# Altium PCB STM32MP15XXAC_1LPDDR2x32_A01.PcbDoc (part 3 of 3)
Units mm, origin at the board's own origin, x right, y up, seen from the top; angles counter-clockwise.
Board outline 89 x 120 mm, 6 copper layers (Top Layer, Signal Layer 1, Signal Layer 2, Signal Layer 3, Signal Layer 4, Bottom Layer), stack 1.556 mm thick; 87 components, 99 nets, 861 pads, 454 vias.
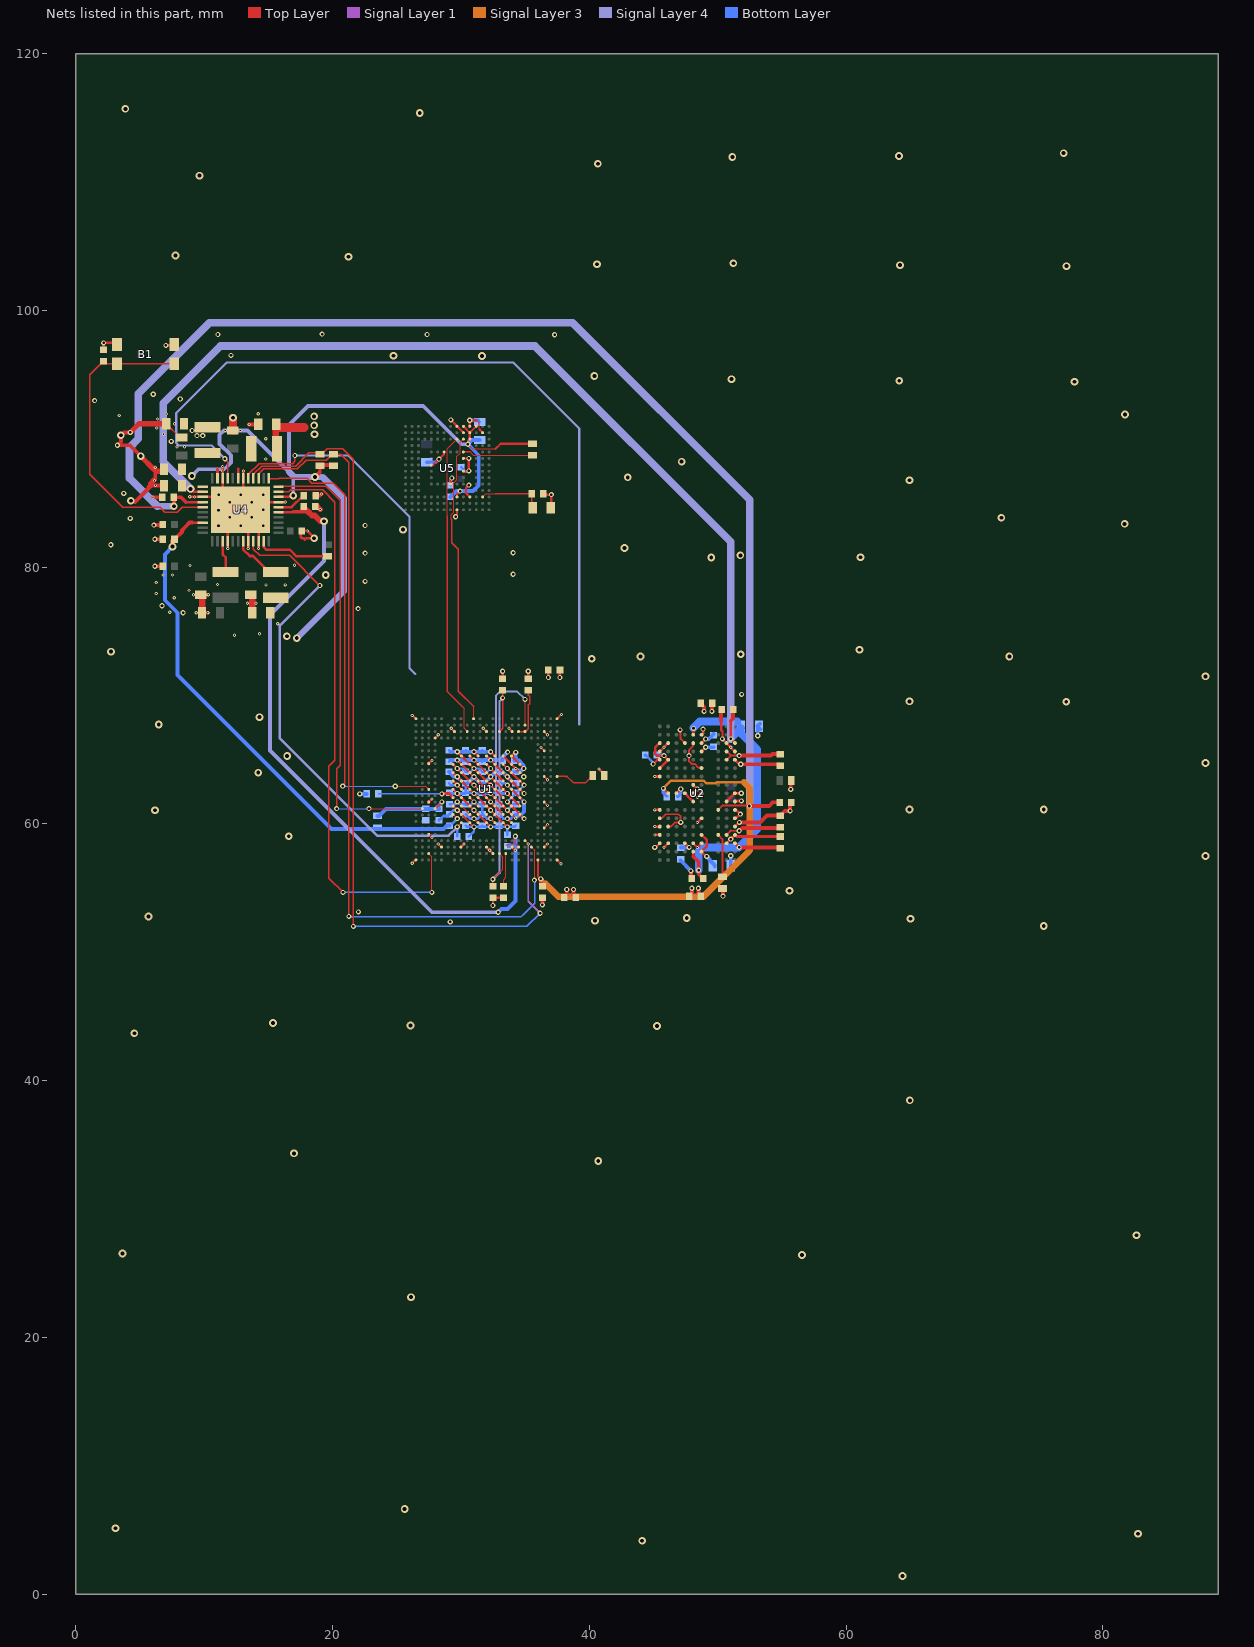
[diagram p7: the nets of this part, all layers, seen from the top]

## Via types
v1: diameter 0.4, hole 0.2, Top Layer to Bottom Layer, tented both sides, 265 vias
v2: diameter 0.6, hole 0.3, Top Layer to Bottom Layer, tented both sides, 102 vias
v3: diameter 0.25, hole 0.1, Top Layer to Signal Layer 1, tented top, 82 vias
v4: diameter 0.25, hole 0.1, Top Layer to Signal Layer 1, tented both sides, 5 vias

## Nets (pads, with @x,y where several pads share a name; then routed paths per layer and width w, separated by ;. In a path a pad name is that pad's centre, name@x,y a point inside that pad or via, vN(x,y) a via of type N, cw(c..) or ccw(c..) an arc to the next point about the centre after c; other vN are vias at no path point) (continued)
GND: B1.1 B1.2 C1.2 C2.2 C3.2 C4.2 C5.2 C6.2 C7.2 C8.2 C9.2 C10.2 C11.2 C12.2 C15.1 C16.1 C17.2 C18.1 C25.2 C26.2 C29.1 C30.1 C31.1 C32.1 C33.1 C34.1 C35.1 C36.1 C37.1 C38.1 C39.1 C40.1 C41.1 C42.1 C43.2 C44.1 C45.1 C46.1 C47.1 C48.1 C49.1 C50.1 C51.1 C52.1 C53.1 C54.1 C55.1 C56.1 C57.1 C58.1 C61.1 C66.1 C67.1 C68.1 C69.1 C70.1 C71.1 C75.1 C76.1 C77.1 C78.1 C79.1 C80.1 C81.1 C82.1 C83.1 C84.1 C92.1 C94.1 C95.1 C96.1 R26.1 R27.2 R29.1 U1.1A3 U1.1A5 U1.1A7 U1.1B2 U1.1B4 U1.1B6 U1.1B8 U1.1C1 U1.1C3 U1.1C5 U1.1C7 U1.1C9 U1.1D2 U1.1D4 U1.1D6 U1.1D8 U1.1E1 U1.1E3 U1.1E5 U1.1E7 U1.1E9 U1.1F2 U1.1F4 U1.1F6 U1.1F8 U1.1G1 U1.1G3 U1.1G5 U1.1G7 U1.1G9 U1.1H2 U1.1H4 U1.1H6 U1.1H8 U1.1J3 U1.1J5 U1.1J7 U1.A1 U1.A23 U1.AA5 U1.AA8 U1.AA12 U1.AA16 U1.AA21 U1.AB13 U1.AC1 U1.AC23 U1.C7 U1.C12 U1.C16 U1.C21 U1.D4 U1.F21 U1.H3 U1.K21 U1.P3 U1.P21 U1.V21 U1.W3 U2.C2 U2.C5 U2.C6 U2.C9 U2.D1 U2.D10 U2.E1 U2.E10 U2.F5 U2.G10 U2.H2 U2.J1 U2.J5 U2.J8 U2.L10 U2.M5 U2.N1 U2.N10 U2.P1 U2.P10 U2.R2 U2.R5 U2.R6 U2.R9 U4.6 U4.10 U4.15 U4.26 U4.30 U4.32 U4.41 U4.ep U5.A6 U5.C4 U5.E7 U5.G5 U5.H10 U5.J5 U5.K8 U5.N2 U5.N5 U5.P4 U5.P6 | length 174.7
  Top Layer w0.09: 31.225,91.45 31.45,91.225 31.45,90.725
  Top Layer w0.12: U1.AA21@36.5,58.2 U1.AA21@36.545,58.2 ; U1.C21@36.5,67.185 U1.C21@36.5,67.2 ; U2.J8@46.8,62.365 U2.J8@46.8,62.4 ; U2.M5@48.709,64.35 U2.M5@48.75,64.35 U2.M5@48.75,64.385 ; C3.2@50.275,68.835 C3.2@50.31,68.87
  Top Layer w0.127: C29.1@7.05,91.175 8.125,90.1 C18.1@8.25,90.1 ; C11.2@47.775,54.375 C11.2@48,54.6 ; C1.2@47.925,55.8 C1.2@47.975,55.75 ; v1(49.55,68.775) v1@49.575,68.8
  Top Layer w0.15: v3(36.25,65.95) U1.F21@36.5,65.7 ; U1.AA21@36.5,58.2 v3(36.75,58.45) ; U1.V21@36.5,59.7 v3(36.75,59.95) ; U1.P21@36.5,61.7 v3(36.75,61.45) ; U1.K21@36.5,63.7 v3@36.735,63.465 ; U1.C21@36.5,67.185 36.742,66.943 v3@36.75,66.935 ; U1.AC23@37.5,57.2 v3(37.795,56.905) ; U1.A23@37.5,68.2 37.837,68.537 v3@37.85,68.55 ; U2.R6@48.1,66.3 48.1,66.1 47.775,65.775 v1(47.775,65.325) 47.775,64.879 47.979,64.675 48.225,64.675 48.5,64.4 48.699,64.4 U2.M5@48.75,64.35
  Top Layer w0.175: v3(26.225,56.95) 26.475,57.2 U1.AC1@26.5,57.2 ; v3(26.225,68.45) 26.25,68.45 U1.A1@26.5,68.2 ; U1.W3@27.5,59.2 v3(27.75,58.95) ; U1.P3@27.5,61.7 v3(27.75,61.95) ; U5.H10@27.7,87.975 27.85,87.975 v1(28.3,88.425) 28.7,88.825 U5.K8@28.7,88.975 ; U1.D4@28,66.7 v3(28.25,66.95) ; v3(28.25,58.45) U1.AA5@28.5,58.2 ; v1(29.225,91.475) 29.7,91 U5.P6@29.7,90.975 U5.N5@30.2,90.475 ; v3(29.25,67.45) U1.C7@29.5,67.2 ; U1.1G1@29.4,61.4 v1(29.725,61.075) U1.1H2@30.05,60.75 U1.1J3@30.7,60.1 v1(31.025,59.775) ; U1.1E1@29.4,62.7 v1(29.725,62.375) U1.1F2@30.05,62.05 U1.1G3@30.7,61.4 v1(31.025,61.075) U1.1H4@31.35,60.75 U1.1J5@32,60.1 v1(32.325,59.775) ; U1.1C1@29.4,64 v1(29.725,63.675) U1.1D2@30.05,63.35 U1.1E3@30.7,62.7 v1(31.025,62.375) U1.1F4@31.35,62.05 U1.1G5@32,61.4 v1(32.325,61.075) U1.1H6@32.65,60.75 U1.1J7@33.3,60.1 v1(33.625,59.775) ; v1(29.6,83.925) 29.7,84.025 U5.A6@29.7,84.475 ; v1(29.725,64.975) U1.1B2@30.05,64.65 U1.1C3@30.7,64 v1(31.025,63.675) U1.1D4@31.35,63.35 U1.1E5@32,62.7 v1(32.325,62.375) U1.1F6@32.65,62.05 U1.1G7@33.3,61.4 v1(33.625,61.075) U1.1H8@33.95,60.75 33.975,60.75 v3(34.275,60.45) ; U5.G5@30.2,87.475 30.601,87.475 v1(30.625,87.5) v1(30.625,88.475) U5.J5@30.2,88.475 ; v1(30.625,86.4) 30.4,86.175 30.4,85.775 U5.C4@30.7,85.475 ; U1.1A3@30.7,65.3 v1(31.025,64.975) U1.1B4@31.35,64.65 U1.1C5@32,64 v1(32.325,63.675) U1.1D6@32.65,63.35 U1.1E7@33.3,62.7 v1(33.625,62.375) U1.1F8@33.95,62.05 U1.1G9@34.6,61.4 ; U5.P4@30.7,90.948 U5.P4@30.7,90.975 v1(30.7,91.45) 31.225,91.45 ; 31.45,90.725 U5.N2@31.7,90.475 ; v3(31.75,67.45) U1.C12@32,67.2 ; U1.1A5@32,65.3 v1(32.325,64.975) U1.1B6@32.65,64.65 U1.1C7@33.3,64 v1(33.625,63.675) U1.1D8@33.95,63.35 U1.1E9@34.6,62.7 v1(34.925,62.375) ; v1(32.5,53.65) C67.1@32.5,54.25 C69.1@33.325,54.25 ; U1.1A7@33.3,65.3 U1.1B8@33.95,64.65 v3(34.275,64.325) U1.1C9@34.6,64 ; v3(33.75,67.45) U1.C16@34,67.2 ; U1.1C9@34.6,63.975 U1.1C9@34.6,64 ; U1.1C9@34.625,64 U1.1C9@34.6,64 ; C82.1@36.425,85.725 36.5,85.65 v1(37.05,85.65) 37.05,84.675 C83.1@37,84.625 ; v3(40.755,64.283) R27.2@41.209,63.829 ; 50.285,67.305 50.376,67.213 v1(50.375,66.625) 50.376,66.612 U2.R2@50.692,66.296
  Top Layer w0.2: C44.1@2.175,96.95 v1(2.175,97.475) 3.1,97.475 B1.1@3.225,97.35 ; v1(7.025,97.275) 7.6,97.275 B1.2@7.675,97.35 ; v4(8.882,85.482) 9.243,85.482 v4(9.25,85.475) U4.15@9.9,85.475 10.875,85.475 U4.ep@10.9,85.45 ; v3@11.45,87.825 v3(11.45,87.5) U4.10@11.45,86.925 11.45,85.875 12.125,85.2 v1(12.85,84.475) ; v3(11.85,81.45) U4.26@11.85,82.025 11.85,83.475 12.125,83.75 v1(12.85,84.475) ; v2(12.255,91.64) v2@12.381,91.514 ; v3@13.05,87.5 U4.6@13.05,86.925 13.05,85.65 U4.ep@13.05,84.675 ; v3@13.45,81.425 v3(13.45,81.45) U4.30@13.45,82.025 U4.ep@13.45,83.875 ; v3(14.25,81.45) U4.32@14.25,82.025 14.25,83.075 13.587,83.738 U4.ep@13.45,83.875 ; v3(16.325,85.075) U4.41@15.8,85.075 v1(13.725,85.075) 13.45,85.075 U4.ep@13.05,84.675 ; C51.1@17.537,82.762 17.537,82.338 17.625,82.25 17.757,82.25 17.857,82.15 17.957,82.25 v2(18.575,82.25) ; C51.1@17.6,82.825 v3(18.05,82.825) v2@18.6,82.275 ; U1.H3@27.5,64.7 v3(27.75,64.95) ; U5.E7@29.2,86.475 29.2,86.825 29.312,86.937 v1@29.325,86.95 ; U1.AA8@30,58.2 v3(30.25,58.45) ; U1.AA12@32,58.2 v3(32.25,57.95) U1.AB13@32.5,57.7 ; C66.1@33.25,71.3 v1(33.25,71.9) ; U1.AA16@34,58.2 v3(34.25,57.95) ; C68.1@35.25,71.3 v1(35.25,71.9) ; v1(37.715,71.41) C12.2@37.715,71.981 ; v1(44.975,64.675) 45.3,65 U2.N10@45.5,65 ; v3@45.103,61.105 45.105,61.105 U2.G10@45.449,61.105 ; v3@45.105,59.15 v3(45.115,59.15) U2.D10@45.5,59.15 ; v3@45.11,63.7 U2.L10@45.5,63.7 ; v3@45.113,59.8 U2.E10@45.5,59.8 ; U2.P10@45.5,65.65 45.5,65.657 45.821,65.979 46.146,66.303 U2.R9@46.157,66.314 ; v3(45.825,58.175) U2.C9@46.15,58.5 ; U2.J8@46.8,62.4 v1(47.125,62.725) ; U2.C6@48.1,58.5 v3(48.425,58.175) U2.C5@48.75,58.5 ; v3@48.418,60.118 v3(48.425,60.125) U2.F5@48.75,60.45 ; v3(48.425,62.085) U2.J5@48.744,62.405 ; U2.R5@48.75,66.3 49.065,66.615 v1@49.075,66.625 ; 50.285,67.305 50.285,68.001 ; U2.C2@50.7,58.5 v1(51.025,58.825) 51.3,59.1 51.35,59.1 51.425,59.1 51.5,59.025 C2.2@54.85,59.025 ; U2.H2@50.7,61.75 U2.J1@51.35,62.4 v1@51.83,62.4 ; U2.R2@50.7,66.3 v3(51.025,65.975) ; v3@51.025,65.97 U2.P1@51.345,65.65 ; U2.E1@51.35,59.8 51.675,60.125 v1(51.7,60.125) ; U2.N1@51.35,65 51.7,64.65 v1(51.8,64.65) 52.095,64.65 ; v1(12.85,84.475) U4.ep@13.05,84.675 ; v1(12.85,84.475) U4.ep@13.45,83.875
  Top Layer w0.3: v1(4.25,90.5) 3.75,90.5 v2(3.525,90.275) 3.525,89.775 v1(3.25,89.5) 4.225,89.5 v2(5.075,88.65) ; v2(4.3,85.175) 4.525,85.175 4.625,85.075 5.675,86.125 ; v3(6.025,85.45) C84.1@6.75,85.45 ; v1(6.1,83.275) 6.75,83.275 C41.1@6.8,83.325 C41.1@6.775,83.35 ; v3(6.144,86.744) 5.925,86.525 5.925,86.5 ; v1(6.175,80.075) C32.1@6.8,80.075 ; v1(6.175,82.175) C49.1@6.8,82.175 ; v3(6.2,87.775) 6.2,87.525 6.2,86.95 ; C46.1@6.85,86.375 v3(6.214,86.375) 5.925,86.375 ; C39.1@9.75,77.85 v3(10.325,77.85) ; C40.1@9.85,76.45 v3(10.3,76.45) ; C33.1@12.255,90.701 12.25,90.696 12.227,90.673 C33.1@12.25,90.65 C33.1@12.4,90.5 ; v3@13.5,91.125 v3(13.525,91.125) 13.95,91.125 14.075,91 C34.1@14.2,90.875 ; C43.2@18.6,85.575 18.649,85.526 C43.2@18.65,85.525 ; C43.2@18.684,85.562 19.012,85.562 v3(19.15,85.7) ; v1(36.35,53.7) C17.2@36.35,54.25 ; C9.2@38.05,54.275 38.25,54.475 v1(38.25,54.9) ; C1.2@47.925,55.8 v1(47.925,56.35) ; C11.2@48,54.6 v1(48,55) ; U2.J5@48.744,62.405 48.75,62.405 U2.J5@48.766,62.405 ; v1@49.575,68.8 C10.2@49.575,69.4 ; 50.275,67.998 C3.2@50.275,68.835 ; v1(50.423,54.387) 50.423,54.975 R29.1@50.423,54.98 ; v1(51.7,60.125) 53.315,60.125 53.84,60.65 54.85,60.65 54.862,60.662 55.225,61.025 v1(55.65,61.025) 55.65,61.625 C26.2@55.725,61.7 ; 52.095,64.65 54.775,64.65 C7.2@54.875,64.55 ; v1(55.7,62.7) R26.1@55.7,63.375 ; 5.675,86.125 5.675,86.25 5.863,86.438 ; 5.675,86.125 5.925,86.375 ; 5.863,86.438 5.925,86.5 ; 5.863,86.438 5.925,86.375 ; 5.863,86.438 5.775,86.525 6.069,86.819 6.2,86.95 ; 5.925,86.375 5.925,86.5 ; 5.925,86.5 6.157,86.732 6.2,86.775 6.2,86.95
  Top Layer w0.4: v1(4.25,90.5) 4.925,91.175 6.325,91.175 C29.1@7.05,91.175 ; v2(5.075,88.65) 6.075,87.65 6.2,87.525 6.25,87.475 C42.1@6.6,87.475 ; C52.1@18.751,84.801 v3(19.053,84.5)
  Top Layer w0.5: C39.1@9.75,77.85 9.85,77.75 C40.1@9.85,76.45 ; C31.1@13.625,77.85 13.625,77.75 13.75,77.625 13.75,77.2 C38.1@13.75,76.45
  Top Layer w0.6: C33.1@12.25,90.65 12.25,90.696 12.25,91.635 v2(12.255,91.64)
  Bottom Layer w0.127: C16.1@53.125,67.525 53.166,67.566 C16.1@53.225,67.625
  Bottom Layer w0.175: C35.1@29.075,64.85 C35.1@29.2,64.975 ; C37.1@30.225,63.175 C37.1@30.375,63.175 C37.1@30.525,63.175 ; C96.1@30.375,59.875 C96.1@30.475,59.775 ; C47.1@30.625,59.025 31.025,59.425 v1(31.025,59.775) ; C81.1@31.325,91.45 C81.1@31.475,91.3 ; C36.1@31.525,63.175 C36.1@31.675,63.175 C36.1@31.825,63.175 ; C76.1@31.55,64.975 C76.1@31.675,64.85 C76.1@31.8,64.975 ; C95.1@31.575,59.775 C95.1@31.675,59.875 C95.1@31.775,59.775 ; C45.1@32.725,64.075 C45.1@32.975,64.075 C45.1@33.225,64.075 ; C55.1@32.875,59.775 C55.1@32.975,59.875 C55.1@33.075,59.775 ; C53.1@33.25,65.2 33.25,64.975 C53.1@33.275,64.95 ; C57.1@34.125,63.175 C57.1@34.275,63.175 ; C54.1@34.175,59.775 C54.1@34.275,59.875
  Bottom Layer w0.2: C58.1@28.3,60.35 C58.1@28.3,60.275 28.65,60.625 28.975,60.625 C70.1@29.125,60.775 29.425,61.075 v1(29.725,61.075) ; C94.1@29.125,62.425 29.175,62.375 v1(29.725,62.375) 30.325,62.375 C48.1@30.375,62.425 ; C80.1@29.2,86.375 29.2,86.825 29.312,86.937 v1@29.325,86.95 ; C78.1@30.025,87.8 30.35,87.475 30.6,87.475 v1(30.625,87.5) ; C37.1@30.375,63.175 C48.1@30.375,62.425 ; C96.1@30.475,59.775 v1(31.025,59.775) C95.1@31.575,59.775 ; C92.1@31.675,62.425 C92.1@31.725,62.375 ; C95.1@31.775,59.775 v1(32.325,59.775) C55.1@32.875,59.775 ; C55.1@33.075,59.775 v1(33.625,59.775) ; C71.1@33.625,59.175 v1(33.625,59.775) ; v1(33.625,61.075) 34.075,61.525 C56.1@34.275,61.525 ; v1(33.625,62.375) 33.025,62.375 C77.1@32.975,62.425 32.375,62.425 v1(32.325,62.375) C92.1@31.725,62.375 ; C54.1@34.175,59.775 v1(33.625,59.775) ; C6.2@44.402,65.36 44.982,64.78 44.982,64.675 v1@44.982,64.652 ; C48.1@30.375,62.425 30.975,62.425 v1(31.025,62.375) 31.675,62.375 C92.1@31.725,62.375
  Bottom Layer w0.3: v1(22.125,62.35) C61.1@22.675,62.35 ; C79.1@27.35,88.175 28.05,88.175 v1(28.3,88.425) ; C75.1@29.075,64.075 29.475,63.675 v1(29.725,63.675) C37.1@30.225,63.175 ; C35.1@29.2,64.975 v1(29.725,64.975) 30.375,64.975 v1(31.025,64.975) C76.1@31.55,64.975 ; C37.1@30.525,63.175 v1(31.025,63.675) C36.1@31.525,63.175 ; v1(30.7,91.45) C81.1@31.325,91.45 ; C76.1@31.8,64.975 v1(32.325,64.975) C53.1@33.25,64.975 ; C36.1@31.825,63.175 v1(32.325,63.675) C45.1@32.725,64.075 ; C45.1@33.225,64.075 v1(33.625,63.675) C57.1@34.125,63.175 ; C53.1@33.25,65.2 v1(33.65,65.6) ; C6.2@44.364,65.36 C6.2@44.402,65.36 ; C25.2@46.905,62.174 47.127,62.396 47.127,62.725 v1@47.127,62.727 ; C4.2@47.102,57.177 v1@47.927,56.352 ; v1@49.064,66.627 49.309,66.627 49.629,66.946 C5.2@49.685,67.003 ; C15.1@51.027,56.717 51.027,56.75 51.027,57.525 v1@51.027,57.527 ; C16.1@53.103,67.628 53.166,67.566 C16.1@53.348,67.383 ; v1(53.125,66.875) C16.1@53.125,67.525 ; C16.1@53.152,67.667 53.167,67.683 C16.1@53.295,67.81
  other v1: 29.175,52.375 22.025,53.15 51.025,57.525 51.845,62.4 34.9,63.675 49.06,66.62 51.875,70.1 8.375,76.45 22,76.775 6.725,77 22.55,78.9 34.075,79.45 22.55,81.1 34.075,81.125 2.75,81.75 11.125,83.225 12.875,83.225 14.6,83.225 22.55,83.25 4.25,83.801 12,83.875 13.725,83.875 11.125,84.45 14.6,84.475 12,85.075 11.15,85.65 12.875,85.65 14.6,85.65 3.75,85.75 29.3,86.95 7.45,89.8 1.475,92.975 8.15,93.1 6.05,93.475 12.1,96.5 37.3,98.1 11.075,98.125 27.375,98.125 19.2,98.15
  other v2: 64.4,1.425 44.125,4.175 82.75,4.725 3.1,5.15 25.625,6.65 26.125,23.15 56.575,26.425 3.65,26.55 82.625,27.975 40.7,33.75 17,34.35 64.975,38.475 4.575,43.7 45.275,44.275 26.075,44.3 15.375,44.5 75.4,52.05 40.452,52.475 65.025,52.625 47.597,52.681 5.675,52.8 55.6,54.8 88,57.5 16.6,59.05 6.175,61.075 64.95,61.125 75.4,61.125 14.225,64 88,64.75 16.475,65.3 6.475,67.75 14.325,68.325 77.15,69.525 64.95,69.55 88,71.5 40.2,72.875 44,73.05 72.725,73.05 51.8,73.225 2.75,73.425 61.05,73.575 19.475,79.4 49.5,80.75 61.125,80.775 51.775,80.925 42.75,81.5 25.5,82.925 81.7,83.375 72.1,83.85 64.95,86.775 43,87 47.2,88.225 81.725,91.9 77.8,94.45 64.15,94.525 51.075,94.65 40.4,94.9 31.65,96.45 24.75,96.475 77.175,103.45 64.2,103.525 40.6,103.6 51.225,103.675 21.25,104.175 7.775,104.275 9.65,110.5 40.675,111.425 51.15,111.95 64.125,112.025 76.95,112.25 26.8,115.375 3.875,115.7
  other v3: 45.105,59.8 45.105,61.1 36.75,63.45 45.105,63.7 45.825,65.975 36.75,66.95 37.85,68.525 12.375,74.7 14.325,74.825 15.75,75.6 9.4,76.45 13.375,77.2 14.05,77.2 7.675,77.625 9.175,77.85 8.825,78.175 14.825,78.625 16.325,78.625 11.05,78.65 6.8,79.4 7.55,79.4 8.911,80.125 17.05,80.15 13.075,87.5 11.45,87.85 14.8,88.425 7.9,89.375 8.475,89.375 14.8,90 6.85,90.35 11.65,90.65 12.825,90.65 6.325,90.85 7.7,91.175 6.375,91.55 3.4,91.825 7.05,91.925 14.225,91.95
  other v4: 7.325,76.5 6.275,77.95 6.275,78.8
I2C4_SCL: R37.2 U1.Y18 U4.4 | length 66.8
  Top Layer w0.09: U1.Y18@35,58.7 v3(35.25,58.45)
  Top Layer w0.1: U4.4@13.85,86.925 13.85,87.237 14.488,87.875 17.125,87.875 18.15,88.9 19.025,88.9 19.26,88.9 19.6,89.24 20.81,89.24 21.638,88.413 v1(21.638,52.025)
  Signal Layer 1 w0.1: v3(35.25,58.45) 35.25,53.975 v1(36.175,53.05)
  Bottom Layer w0.1: v1(21.638,52.025) 35.15,52.025 v1(36.175,53.05)
I2C4_SDA: R38.2 U1.AA19 U4.3 | length 63.2
  Top Layer w0.09: U1.AA19@35.5,58.2 35.75,57.95 v1@35.75,55.625
  Top Layer w0.1: U4.3@14.25,86.925 14.25,87.267 14.658,87.675 17.275,87.675 17.95,88.35 19.525,88.35 20.012,88.838 R38.2@19.975,88.875 ; R38.2@20.074,88.813 20.637,88.813 21.288,88.162 v1(21.288,52.8)
  Bottom Layer w0.1: 34.813,52.888 35.75,53.825 35.75,55.625 v1@35.75,55.775
  Bottom Layer w0.12: v1(21.288,52.8) 21.323,52.765 34.69,52.765 34.813,52.888
  other v1: 35.725,55.625
NetB1_3: B1.3 B1.4 C44.2 U4.17 | length 24.9
  Top Layer w0.1: B1.4@7.675,95.85 B1.3@3.225,95.85 2.175,95.85 1.95,95.85 1.1,95 1.1,87.25 3.675,84.675 6.575,84.675 6.95,84.3 7.925,84.3 8.3,84.675 U4.17@9.9,84.675
NetC43_1: C43.1 U4.40 | length 2.2
  Top Layer w0.2: U4.40@15.8,84.675 16.828,84.675 C43.1@17.689,85.536
NetC61_2: C61.2 U1.1F1 | length 6
  Top Layer w0.2: v1@28.55,62.375 29.075,62.375 U1.1F1@29.4,62.05
  Top Layer w0.3: v1@28.475,62.35 v1(28.525,62.35) v1@28.55,62.375
  Bottom Layer w0.1: C61.2@23.575,62.35 v1(28.525,62.35)
NetC68_2: C68.2 U1.C17 U1.C18 | length 3.9
  Top Layer w0.1: U1.C17@34.5,67.2 U1.C18@35,67.2 35.025,67.2 35.25,67.425 35.25,69.275 35.35,69.375 35.35,69.945 35.25,70.045 C68.2@35.25,70.4
NetC69_2: C69.2 U1.AB15 | length 2.6
  Top Layer w0.09: C69.2@33.325,55.15 33.325,55.675 33.5,55.85 U1.AB15@33.5,57.7
NetC82_2: C82.2 C83.2 U5.C2 | length 5.1
  Top Layer w0.09: U5.C2@31.7,85.475 31.95,85.725 32.7,85.725
  Top Layer w0.1: 32.7,85.725 C82.2@35.525,85.725 35.525,84.7 C83.2@35.6,84.625
NetL1_1: L1.1 U4.7 | length 0.7
  Top Layer w0.2: U4.7@12.65,86.925 12.65,87.672
NetL2_1: L2.1 U4.11 | length 0.7
  Top Layer w0.2: U4.11@11.05,86.925 11.05,87.65
NetL3_1: L3.1 U4.29 | length 3.9
  Top Layer w0.2: U4.29@13.05,82.025 13.05,81.39 13.565,80.875 13.8,80.875 15.05,79.625 L3.1@15.575,79.625
NetL4_1: L4.1 U4.25 | length 2.4
  Top Layer w0.2: U4.25@11.45,82.025 11.45,81 11.675,80.775 L4.1@11.675,79.725
NetR27_1: R27.1 U1.K23 | length 3.3
  Top Layer w0.1: U1.K23@37.5,63.7 38.165,63.7
  Top Layer w0.12: 38.165,63.7 38.275,63.7 38.752,63.223 39.723,63.223 R27.1@40.275,63.775 R27.1@40.362,63.862
NetR29_2: R29.2 U2.D3 | length 3.4
  Top Layer w0.15: U2.D3@50.05,59.15 50.375,58.824 R29.2@50.375,55.875
NetR40_1: R40.1 U5.K5 | length 5.5
  Top Layer w0.09: 30.725,88.975 30.975,88.725 R40.1@35.575,88.725
  Top Layer w0.1: U5.K5@30.2,88.975 30.725,88.975
NetR43_1: R43.1 U4.33 | length 5.7
  Top Layer w0.2: U4.33@14.65,82.025 14.65,81.561 14.836,81.375 16.675,81.375 17.2,80.85 R43.1@19.625,80.85
NRST: U1.M3 U4.1 | length 36
  Top Layer w0.09: v1(24.89,62.94) 27.26,62.94 U1.M3@27.5,62.7
  Top Layer w0.1: U4.1@15.05,86.875 15.82,86.875 15.87,86.925 18.025,86.925 18.4,86.55 20.075,86.55 20.975,85.65 20.975,63.125 v1(20.8,62.95)
  Bottom Layer w0.09: v1(20.8,62.95) 24.88,62.95 v1(24.89,62.94)
PA0_WKUP: U1.AB3 U4.43 | length 46
  Top Layer w0.09: U1.AB3@27.5,57.7 27.75,57.45 v1(27.75,54.675)
  Top Layer w0.1: U4.43@15.8,85.875 16.614,85.875 16.764,86.025 19.25,86.025 20.2,85.075 20.2,64.975 19.725,64.5 19.725,55.775 v1(20.825,54.675)
  Bottom Layer w0.1: v1@20.8,54.675 v1(20.825,54.675) v1(27.75,54.675)
PWR_ON: U1.R2 U4.44 | length 36.1
  Top Layer w0.09: v1@22.825,61.2 v1(22.85,61.2) U1.R2@27,61.2
  Top Layer w0.1: U4.44@15.85,86.225 15.925,86.3 19.525,86.3 20.6,85.225 20.6,64.575 20.325,64.3 v1(20.325,61.2)
  Bottom Layer w0.09: v1(20.325,61.2) v1(22.85,61.2)
SDMMC2_CK: U1.C9 U5.M6 | length 23.7
  Top Layer w0.09: 28.95,84 28.95,89.225 U5.M6@29.7,89.975 ; 30.137,69.138 30.25,69.025 30.25,67.45 U1.C9@30.5,67.2
  Top Layer w0.13: 28.95,84 28.95,70.325 30.137,69.138
SDMMC2_CMD: U1.A10 U5.M5 | length 22.9
  Top Layer w0.09: 29.255,83.745 29.255,84.068 29.46,84.273 29.46,86.574 29.7,86.814 29.7,88.636 29.95,88.886 29.95,89.725 U5.M5@30.2,89.975 ; U1.A10@31,68.2 31,69.15
  Top Layer w0.13: 29.255,83.745 29.3,83.7 29.3,81.9 29.8,81.4 29.8,70.35 31,69.15
VDD: C38.2 C42.2 C47.2 C48.2 C80.2 C81.2 C92.2 C94.2 C95.2 C96.2 L3.2 R37.1 R38.1 R40.2 U1.1F3 U1.1G2 U1.1G4 U1.1H3 U1.1H5 U1.1J2 U1.1J4 U1.1J6 U1.B18 U4.13 U4.31 U4.42 U5.C6 U5.M4 U5.N4 U5.P3 U5.P5 | length 133
  Top Layer w0.09: v1(30.55,89.575) 30.9,89.225 32.7,89.225 ; U1.B18@35,67.7 v1(35,69.7) v1@35,69.8
  Top Layer w0.1: U4.31@13.85,82.025 13.85,81.4 14.325,80.925 16.675,80.925 v1(19.025,78.575)
  Top Layer w0.12: v1(29.725,59.775) U1.1J2@30.05,60.1 ; v1(29.725,61.725) U1.1G2@30.05,61.4 U1.1H3@30.7,60.75 v1(31.025,60.425) U1.1J4@31.35,60.1 ; U1.1F3@30.7,62.05 v1(31.025,61.725) U1.1G4@31.35,61.4 ; U1.1H5@32,60.75 v1(32.325,60.425) U1.1J6@32.65,60.1
  Top Layer w0.175: U5.C6@29.7,85.475 29.7,85.675 v1(29.95,85.925) ; U5.P5@30.2,90.975 U5.N4@30.7,90.475 ; v1(30.55,89.575) 30.55,89.825 U5.M4@30.7,89.975 U5.N4@30.7,90.475 ; U5.P3@31.2,90.975 U5.N4@30.7,90.475 ; 32.7,89.225 33.1,89.625 R40.2@35.575,89.625
  Top Layer w0.2: U4.42@15.8,85.475 v2@16.85,85.475 ; v2@16.85,85.475 v2(16.95,85.575) ; v2@16.85,85.475 v2(16.95,85.575) ; v2(16.95,85.575) v2(16.95,85.575) 16.95,85.579 v2(16.95,85.575)
  Top Layer w0.25: 19,87.375 19.025,87.4 R37.1@19.025,87.9
  Top Layer w0.3: v2@18.65,87.15 v2(18.65,87.025) 19,87.375 ; R37.1@19.325,87.95 20.074,87.95 R38.1@20.175,87.95
  Signal Layer 4 w0.15: 32.6,60.675 32.725,60.8 32.725,69.975 33.075,70.325 34.375,70.325 v1(35,69.7)
  Signal Layer 4 w0.2: 16.95,87.1 17.025,87.025 ; v1(19.025,78.575) 15.9,75.45 15.9,66.675 23.475,59.1 29.05,59.1 v1(29.725,59.775)
  Signal Layer 4 w0.3: v2(9.05,87.1) 9.575,87.625 11.575,87.625 12.1,88.15 12.1,88.725 11.217,89.608 11.217,90.317 11.55,90.65 13.4,90.65 16.625,87.425 16.625,91.075 18.1,92.55 27.075,92.55 30.05,89.575 v1(30.55,89.575) ; v2(16.95,85.575) 16.95,87.1
  Signal Layer 4 w0.5: 16.625,87.425 16.95,87.1 ; 17.025,87.025 v2(18.65,87.025) 19.225,87.025 20.875,85.375 20.875,78.125 v2(17.225,74.475)
  Bottom Layer w0.175: C47.2@29.725,59.025 v1(29.725,59.775)
  Bottom Layer w0.2: C94.2@29.125,61.525 29.525,61.525 v1(29.725,61.725) 29.925,61.525 C48.2@30.375,61.525 ; C96.2@30.375,60.775 30.725,60.425 v1(31.025,60.425) 31.325,60.425 C95.2@31.675,60.775 ; C48.2@30.4,61.5 30.8,61.5 v1(31.025,61.725) 31.225,61.525 C92.2@31.675,61.525 C95.2@31.675,60.775 ; v1(32.325,60.425) 32.025,60.425 C95.2@31.675,60.775
  Bottom Layer w0.3: C80.2@29.2,85.475 29.65,85.925 v1(29.95,85.925) 30.95,85.925 31.4,86.375 31.4,88.725 v1(30.55,89.575) 30.875,89.9 C81.2@31.475,89.9
  other v2: 16.45,74.625
VDD1_DDR: C1.1 C2.1 C3.1 C16.2 C46.2 U2.B6 U2.C1 U2.R1 U2.T6 U4.14 | length 105.7
  Top Layer w0.12: v1@48.1,67.434 48.12,67.454 v1@48.124,67.459
  Top Layer w0.15: v1@48.1,67.425 v1(48.125,67.45)
  Top Layer w0.175: v1(51.025,66.625) 51.025,68.025
  Top Layer w0.2: 9.175,85.875 U4.14@9.9,85.875 ; U2.B6@48.1,57.85 48.103,57.846 48.103,57.479 ; U2.T6@48.1,66.95 v1@48.1,67.434 ; v1(51.025,66.625) U2.R1@51.35,66.3 ; U2.C1@51.35,58.5 v1(51.675,58.175)
  Top Layer w0.3: 48.103,57.479 48.535,57.048 48.535,56.4 v1@48.535,56.395 ; v1@48.53,56.39 48.53,56.087 48.871,55.746 C1.1@48.873,55.744 ; 51.025,68.025 51.2,68.2 51.2,68.86 C3.1@51.21,68.87 ; v1(51.675,58.175) C2.1@54.875,58.175
  Signal Layer 4 w0.6: v2(8.95,86.1) 6.825,88.225 6.825,92.775 11.275,97.225 35.775,97.225 51.025,81.975 v1(51.025,66.625)
  Bottom Layer w0.3: v1@51.027,66.627 v1@51.027,66.656 ; C16.2@51.537,67.975 C16.2@51.706,67.806 ; C16.2@51.737,67.661 C16.2@51.8,67.599 ; 51.817,67.058 C16.2@51.817,67.447
  Bottom Layer w0.6: v1@48.1,67.474 48.611,67.985 51.527,67.985 C16.2@51.537,67.975 ; v1@48.525,56.4 48.525,57.9 48.802,58.177 51.652,58.177 51.662,58.187 53.075,59.6 53.075,65.8 51.817,67.058 ; v1@51.027,66.656 C16.2@51.817,67.447
  other v1: 48.525,56.4
VDD2_DDR: C4.1 C5.1 C6.1 C7.1 C8.1 C9.1 C10.1 C11.1 C12.1 C15.2 C29.2 C45.2 C53.2 C54.2 C55.2 C56.2 C57.2 L2.2 U1.1A8 U1.1B7 U1.1B9 U1.1C8 U1.1D9 U1.1E8 U1.1F9 U1.1G8 U1.1H9 U1.1J8 U2.B5 U2.C7 U2.C10 U2.D2 U2.D5 U2.E9 U2.F1 U2.F10 U2.G1 U2.H1 U2.H6 U2.J6 U2.J7 U2.K6 U2.M10 U2.N2 U2.N9 U2.P2 U2.P5 U2.R7 U2.R10 U2.T5 U4.9 | length 116.3
  Top Layer w0.1: v1(11.625,88.45) 11.85,88.225 U4.9@11.85,86.925
  Top Layer w0.12: U2.B5@48.75,57.85 U2.B5@48.75,57.855
  Top Layer w0.15: U1.1H9@34.6,60.75 v1(34.925,60.425) ; U1.1F9@34.6,62.05 v1(34.925,61.725) ; U1.1D9@34.6,63.35 v1(34.925,63.025) ; U2.F10@45.5,60.45 45.638,60.45 45.948,60.76 46.95,60.76 47.125,60.585 v1(47.125,60.13) v1@47.125,60.125 ; U2.E9@46.15,59.8 46.361,59.8 46.671,60.11 v1@47.11,60.11 ; v1@47.076,67.31 47.125,67.261 47.125,66.625 U2.R7@47.45,66.3 ; U2.N2@50.7,65 51.025,65.325 v1(51.675,65.325) ; U2.P2@50.735,65.615 51.01,65.34 ; 51.025,59.475 v1(51.675,59.475) v1@51.7,59.475
  Top Layer w0.175: U1.1B7@33.3,64.65 v1(33.625,64.325) U1.1C8@33.95,64 U1.1D9@34.6,63.35 ; v1(33.625,60.425) U1.1J8@33.95,60.1 ; v1(33.625,61.725) U1.1G8@33.95,61.4 U1.1H9@34.6,60.75 ; v1(33.625,63.025) U1.1E8@33.95,62.7 U1.1F9@34.6,62.05 ; v1(34.275,65.575) 34.225,65.575 U1.1A8@33.95,65.3 U1.1B9@34.6,64.65 ; U1.1B9@34.6,64.625 U1.1B9@34.6,64.65 ; v1@34.9,64.35 U1.1B9@34.6,64.65 ; 45.263,65.325 v1(45.825,65.325)
  Top Layer w0.2: v1(36.815,71.41) C12.1@36.815,71.981 ; v1@45.08,58.175 v1(45.1,58.175) 45.175,58.175 U2.C10@45.499,58.499 ; 45.263,65.325 45.14,65.448 45.14,65.963 U2.R10@45.481,66.304 ; U2.M10@45.5,64.35 U2.N9@46.15,65 v1(45.825,65.325) ; U2.C7@47.45,58.5 v1@47.772,58.177 ; U2.J7@47.45,62.4 47.778,62.075 ; U2.K6@48.1,63.05 v1(48.425,62.725) U2.J6@48.1,62.4 47.778,62.075 ; U2.H6@48.105,61.744 U2.H6@48.1,61.75 47.778,62.075 ; U2.B5@48.75,57.837 v1@49.131,57.456 ; U2.B5@48.75,57.855 49.17,58.275 49.17,58.745 U2.D5@48.765,59.15 ; U2.P5@48.75,65.65 49.068,65.968 v1@49.074,65.974 ; U2.T5@48.75,66.95 48.875,67.075 v1@48.875,67.372 ; U2.D2@50.7,59.15 51.025,59.475 ; U2.F1@51.35,60.45 51.449,60.45 v1(51.775,60.775) 51.45,61.1 U2.G1@51.35,61.1 ; U2.H1@51.35,61.75 51.39,61.79 v1@51.85,61.79
  Top Layer w0.3: v1(38.775,54.9) 38.775,54.45 C9.1@38.95,54.275 ; v1@47.772,58.177 47.775,58.177 v1@47.797,58.177 ; v1(48.5,55) 48.5,54.55 C11.1@48.675,54.375 ; C10.1@48.675,69.4 48.95,69.125 v1(48.95,68.775) ; U2.B5@48.75,57.837 U2.B5@48.75,57.85 ; v1(51.675,65.325) 54.154,65.325 54.279,65.45 C7.1@54.875,65.45 ; v1@51.7,59.475 51.925,59.7 C8.1@54.825,59.7
  Signal Layer 4 w0.175: v1@11.7,88.45 v1(11.625,88.45) 10.6,89.475 8.037,89.475 7.838,89.675 7.838,92.012 11.775,95.95 34.075,95.95 39.225,90.8 39.225,67.775
  Bottom Layer w0.127: 34.7,60.65 34.7,60.725
  Bottom Layer w0.175: C45.2@32.975,63.175 33.475,63.175 v1(33.625,63.025) 33.898,62.752 33.973,62.752 34.275,62.45 C56.2@34.275,62.425 ; v1(33.625,61.725) C56.2@34.275,62.375 ; v1(33.625,64.325) 33.875,64.075 C57.2@34.275,64.075 ; C54.2@34.275,60.775 C54.2@34.325,60.725 ; C53.2@34.275,65.05 C53.2@34.296,65.004 ; v1@34.9,63 34.325,62.425 C56.2@34.275,62.425 ; v1(34.925,61.725) C56.2@34.275,62.375 ; C56.2@34.275,62.375 C56.2@34.275,62.425
  Bottom Layer w0.2: C55.2@32.975,60.775 33.325,60.425 v1(33.625,60.425) 33.925,60.425 C54.2@34.275,60.775 ; 34.7,60.65 v1(34.925,60.425)
  Bottom Layer w0.25: v1@49.064,65.977 49.675,65.977 C5.1@49.694,65.977
  Bottom Layer w0.3: C53.2@34.175,64.95 34.525,64.95 34.9,64.575 v1(34.9,64.325) ; C57.2@34.275,64.075 34.65,64.075 v1@34.887,64.312 ; C53.2@34.275,65.05 v1(34.275,65.575) ; C54.2@34.325,60.725 34.7,60.725 34.925,60.95 v1(34.925,61.725) ; C6.1@45.264,65.36 45.818,65.36 v1@45.838,65.339 ; C4.1@47.152,58.177 47.775,58.177 v1@47.777,58.177 ; v1@49.13,57.455 49.73,56.855 49.782,56.803 49.782,56.75 C15.2@49.782,56.683
  other v1: 49.15,57.475 47.775,58.175 51.85,61.8 49.062,65.975 47.075,67.325 48.86,67.385 9.45,90.25 9.9,90.25 9.075,90.65
VDD_CORE: C30.2 C34.2 C35.2 C36.2 C37.2 C75.2 C76.2 C77.2 L1.2 U1.1A2 U1.1A4 U1.1A6 U1.1B1 U1.1B3 U1.1B5 U1.1C2 U1.1C4 U1.1C6 U1.1D1 U1.1D3 U1.1D5 U1.1D7 U1.1E2 U1.1E4 U1.1E6 U1.1F5 U1.1F7 U1.1G6 U1.1H7 U4.5 | length 54.1
  Top Layer w0.1: U4.5@13.45,86.925 13.45,87.237 14.288,88.075 16.9,88.075 17.075,88.25 v1(17.075,88.7)
  Top Layer w0.175: U1.1D1@29.4,63.35 v1(29.725,63.025) U1.1E2@30.05,62.7 ; U1.1B1@29.4,64.65 v1(29.725,64.325) U1.1C2@30.05,64 U1.1D3@30.7,63.35 v1(31.025,63.025) U1.1E4@31.35,62.7 U1.1F5@32,62.05 v1(32.325,61.725) U1.1G6@32.65,61.4 U1.1H7@33.3,60.75 ; v1(29.725,65.625) U1.1A2@30.05,65.3 U1.1B3@30.7,64.65 v1(31.025,64.325) U1.1C4@31.35,64 U1.1D5@32,63.35 v1(32.325,63.025) U1.1E6@32.65,62.7 U1.1F7@33.3,62.05 ; v1(31.025,65.625) U1.1A4@31.35,65.3 ; U1.1B5@32,64.65 v1(32.325,64.325) U1.1C6@32.65,64 U1.1D7@33.3,63.35 ; v1(32.325,65.625) U1.1A6@32.65,65.3
  Top Layer w0.5: C34.2@15.6,90.875 15.6,89.3 L1.2@15.675,89.225
  Top Layer w0.7: C34.2@15.675,90.875 17.775,90.875
  Signal Layer 4 w0.175: v1(17.075,88.7) 21.225,88.7 26,83.925 26,72.125 26.45,71.675
  Bottom Layer w0.175: C75.2@29.075,63.175 29.225,63.025 v1(29.725,63.025) ; C35.2@29.075,65.75 C35.2@29.2,65.625 ; v1(29.725,64.325) 30.125,64.325 C37.2@30.375,64.075 30.775,64.075 v1(31.025,64.325) 31.425,64.325 C36.2@31.675,64.075 32.075,64.075 v1(32.325,64.325) ; C30.2@30.25,65.625 C30.2@30.375,65.75 C30.2@30.5,65.625 ; C76.2@31.55,65.625 C76.2@31.675,65.75 C76.2@31.8,65.625
  Bottom Layer w0.2: v1(32.325,61.725) 32.525,61.525 C77.2@32.975,61.525
  Bottom Layer w0.3: C35.2@29.2,65.625 v1(29.725,65.625) C30.2@30.25,65.625 ; C30.2@30.5,65.625 v1(31.025,65.625) C76.2@31.55,65.625 ; C76.2@31.8,65.625 v1(32.325,65.625)
  other v2: 18.6,90.35 18.575,91.05 18.575,91.75
VDD_USB: C52.2 C71.2 U1.AA15 U1.AA17 U4.39 | length 57.9
  Top Layer w0.09: U1.AA15@33.5,58.2 33.75,58.45 34.25,58.45 ; v1@34.25,59.125 v1(34.25,59.05) 34.25,58.45 ; U1.AA17@34.5,58.2 34.25,58.45
  Top Layer w0.2: U4.39@15.8,84.275 16.85,84.275 ; C52.2@17.625,84.575 C52.2@17.775,84.725 C52.2@17.775,84.66 ; 16.85,84.275 18.075,84.275 18.117,84.317 18.175,84.375 18.059,84.375 17.775,84.375 16.95,84.375 16.85,84.275
  Top Layer w0.45: C52.2@17.775,84.66 17.775,84.659 18.059,84.375 18.117,84.317 18.409,84.025 18.625,84.025 19.075,83.575 v2(19.35,83.575)
  Signal Layer 4 w0.3: v2(19.35,83.575) 19.35,80.475 15.15,76.275 15.15,65.725 27.75,53.125 v1(32.9,53.125)
  Bottom Layer w0.3: v1(32.9,53.125) 33.155,53.38 33.63,53.38 34.25,54 v1(34.25,59.05) ; C71.2@33.625,58.275 34.225,58.275
VDDA: C49.2 C70.2 R41.1 U1.1H1 U4.20 | length 41.4
  Top Layer w0.09: U1.1H1@29.4,60.75 v1(29.725,60.425)
  Top Layer w0.2: 9.075,83.475 U4.20@9.9,83.475
  Top Layer w0.3: C49.2@7.7,82.175 8.275,82.75 8.275,82.873 8.55,83.148 8.55,83.155 8.87,83.475 9.075,83.475
  Top Layer w0.4: v2(7.55,81.6) 7.55,82.025 C49.2@7.7,82.175
  Bottom Layer w0.2: C70.2@29.35,60.05 v1(29.725,60.425)
  Bottom Layer w0.3: v2(7.55,81.6) 6.95,81 6.95,77.425 7.925,76.45 7.925,71.6 19.925,59.6 23.5,59.6 28.65,59.6 28.925,59.875 C70.2@29.125,59.875
VDDA_1V8: C66.2 C67.2 U1.AB14 U1.C14 | length 20.7
  Top Layer w0.09: C67.2@32.5,55.15 v1(32.5,55.7) 33.275,56.475 33.275,57.425 U1.AB14@33,57.7
  Top Layer w0.1: U1.C14@33,67.2 33.25,67.45 v1(33.25,69.825) C66.2@33.25,70.4
  Signal Layer 4 w0.1: v1@33.25,69.8 v1(33.25,69.825)
  Signal Layer 4 w0.15: 33.025,56.225 33.025,69.575 v1@33.25,69.8
  Signal Layer 4 w0.2: v1(32.5,55.7) 33.025,56.225
VREF+: C50.2 C58.2 R41.2 U1.R4 | length 6.5
  Top Layer w0.1: U1.R4@28,61.2 28.025,61.2 28.537,61.713 v1@28.575,61.75
  Bottom Layer w0.2: C58.2@28.3,61.175 28.3,61.5 v1(28.525,61.725)
  Bottom Layer w0.3: R41.2@23.5,60.625 23.625,60.625 24.175,61.175 C50.2@27.275,61.175 C58.2@28.3,61.175
VREF_DDR: C17.1 C25.1 C26.1 C84.2 U1.AC20 U2.G3 U2.J9 U4.16 | length 132.9
  Top Layer w0.12: U2.J9@46.15,62.4 U2.J9@46.15,62.422
  Top Layer w0.127: C17.1@36.225,55.275 C17.1@36.35,55.15 ; v1@36.225,55.7 v1(36.225,55.725)
  Top Layer w0.15: U1.AC20@36,57.2 36,55.925 36.213,55.712 v1@36.225,55.7 ; U2.G3@50.05,61.1 50.375,61.425 52.475,61.425 v1@52.5,61.425
  Top Layer w0.2: 8.575,85.075 U4.16@9.9,85.075 ; v1@45.782,62.789 45.785,62.786 U2.J9@46.15,62.422
  Top Layer w0.3: v2(7.65,84.75) C84.2@7.65,85.45 8.2,85.45 8.575,85.075 ; C17.1@36.225,55.275 v1@36.225,55.7 ; v1@52.5,61.4 54.025,61.4 54.325,61.7 C26.1@54.8,61.7
  Signal Layer 3 w0.127: v1@45.771,62.767 45.776,62.773 45.78,62.776 v1@45.78,62.797
  Signal Layer 3 w0.2: v1@45.774,62.782 45.778,62.778 v1@45.78,62.776 ; v1@45.78,62.797 46.345,63.361 48.937,63.361 49.109,63.19 49.894,63.19 49.951,63.247 52.053,63.247 52.22,63.247
  Signal Layer 3 w0.3: v1(36.225,55.725) 36.6,55.35
  Signal Layer 3 w0.5: 36.6,55.35 37.6,54.35 48.903,54.35 52.493,57.94 52.493,61.4 52.493,62.807 52.053,63.247
  Signal Layer 4 w0.5: 6.375,84.75 v2(7.65,84.75)
  Signal Layer 4 w0.6: 6.375,84.75 4.2,86.925 4.2,89.325 4.875,90 4.875,93.5 10.425,99.05 38.7,99.05 52.5,85.25 v1@52.5,61.4
  Bottom Layer w0.3: v1@45.777,62.777 45.777,62.775 45.777,62.441 C25.1@46.019,62.199
  other v1: 52.475,61.4 45.775,62.775
pads on no net: U1.A2 U1.A3 U1.A4 U1.A5 U1.A7 U1.A8 U1.A14 U1.A16 U1.A17 U1.A19 U1.A20 U1.AA1 U1.AA2 U1.AA3 U1.AA4 U1.AA6 U1.AA7 U1.AA9 U1.AA10 U1.AA11 U1.AA13 U1.AA14 U1.AA18 U1.AB1 U1.AB2 U1.AB4 U1.AB5 U1.AB6 U1.AB7 U1.AB8 U1.AB9 U1.AB10 U1.AB11 U1.AB12 U1.AB16 U1.AB17 U1.AB18 U1.AB19 U1.AC2 U1.AC3 U1.AC4 U1.AC5 U1.AC7 U1.AC8 U1.AC10 U1.AC11 U1.AC13 U1.AC14 U1.AC16 U1.AC17 U1.AC19 U1.B1 U1.B2 U1.B3 U1.B4 U1.B5 U1.B6 U1.B7 U1.B8 U1.B9 U1.B14 U1.B15 U1.B16 U1.B17 U1.B19 U1.B20 U1.C1 U1.C2 U1.C3 U1.C4 U1.C5 U1.C6 U1.C8 U1.C10 U1.C15 U1.C19 U1.C20 U1.D1 U1.D2 U1.D3 U1.D5 U1.D6 U1.D7 U1.D8 U1.D9 U1.D10 U1.D11 U1.D12 U1.D13 U1.D14 U1.D15 U1.D16 U1.D17 U1.D18 U1.D19 U1.D20 U1.E1 U1.E2 U1.E3 U1.E4 U1.F2 U1.F3 U1.F4 U1.F20 U1.G1 U1.G2 U1.G3 U1.G4 U1.H1 U1.H2 U1.H4 U1.J2 U1.J3 U1.J4 U1.K1 U1.K2 U1.K3 U1.K4 U1.K20 U1.L1 U1.L2 U1.L3 U1.L4 U1.L21 U1.L22 U1.L23 U1.M2 U1.M4 U1.M20 U1.M21 U1.N1 U1.N2 U1.N3 U1.N4 U1.N20 U1.N21 U1.P1 U1.P2 U1.P4 U1.P20 U1.P23 U1.R3 U1.R20 U1.R21 U1.R22 U1.T1 U1.T2 U1.T3 U1.T4 U1.U1 U1.U2 U1.U3 U1.U4 U1.U20 U1.V2 U1.V3 U1.V4 U1.W1 U1.W2 U1.W4 U1.Y1 U1.Y2 U1.Y3 U1.Y4 U1.Y5 U1.Y6 U1.Y7 U1.Y8 U1.Y9 U1.Y10 U1.Y11 U1.Y12 U1.Y13 U1.Y14 U1.Y15 U1.Y16 U1.Y17 U1.Y19 U2.A1 U2.A2 U2.A9 U2.A10 U2.B1 U2.B2 U2.B3 U2.B10 U2.C3 U2.J2 U2.K2 U2.K3 U2.L2 U2.L3 U2.R3 U2.T1 U2.T2 U2.T3 U2.T10 U2.U1 U2.U2 U2.U9 U2.U10 U4.2 U4.18 U4.21 U4.23 U4.34 U4.35 U4.38 U5.A1 U5.A2 U5.A7 U5.A8 U5.A9 U5.A10 U5.A11 U5.A12 U5.A13 U5.A14 U5.B1 U5.B7 U5.B8 U5.B9 U5.B10 U5.B11 U5.B12 U5.B13 U5.B14 U5.C1 U5.C3 U5.C5 U5.C7 U5.C8 U5.C9 U5.C10 U5.C11 U5.C12 U5.C13 U5.C14 U5.D1 U5.D2 U5.D3 U5.D4 U5.D12 U5.D13 U5.D14 U5.E1 U5.E2 U5.E3 U5.E5 U5.E8 U5.E9 U5.E10 U5.E12 U5.E13 U5.E14 U5.F1 U5.F2 U5.F3 U5.F10 U5.F12 U5.F13 U5.F14 U5.G1 U5.G2 U5.G3 U5.G10 U5.G12 U5.G13 U5.G14 U5.H1 U5.H2 U5.H3 U5.H5 U5.H12 U5.H13 U5.H14 U5.J1 U5.J2 U5.J3 U5.J12 U5.J13 U5.J14 U5.K1 U5.K2 U5.K3 U5.K6 U5.K7 U5.K10 U5.K12 U5.K13 U5.K14 U5.L1 U5.L2 U5.L3 U5.L12 U5.L13 U5.L14 U5.M1 U5.M2 U5.M3 U5.M7 U5.M8 U5.M9 U5.M10 U5.M11 U5.M12 U5.M13 U5.M14 U5.N1 U5.N3 U5.N6 U5.N7 U5.N8 U5.N9 U5.N10 U5.N11 U5.N12 U5.N13 U5.N14 U5.P1 U5.P2 U5.P7 U5.P8 U5.P9 U5.P10 U5.P11 U5.P12 U5.P13 U5.P14

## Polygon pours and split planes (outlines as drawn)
5V_VIN on Top Layer "NO TR" (solid, remove dead copper, pour order 180): 12.35,88.125 12.35,88.4 13.025,89.075 13.025,90.125 12.925,90.225 11.675,90.225 11.5,90.05 11.5,89.1 12.15,88.45 12.15,88.125
3V3 on Top Layer "NO TR" (solid, remove dead copper, pour order 178): 11.75,74.55 12.725,75.525 12.725,78.15 10.625,78.15 10.625,75.9 10.45,75.725 9.725,75.725 9.725,74.675 9.85,74.55
VDD_CORE on Top Layer "NO TR" (solid, remove dead copper, pour order 174): 17.5,89.95 17.5,91.564 18.063,92.127 18.748,92.127 19.05,91.825 19.05,89.925 18.9,89.775 17.675,89.775
VDD on Top Layer "NO TR" (solid, remove dead copper, pour order 172): 14.55,78.1 17.25,78.1 17.875,77.475 17.875,74.35 17.525,74 16.6,74 16.1,74.5 16.1,75.95 14.55,75.95
NetL4_1 on Top Layer "NO TR" (solid, remove dead copper, pour order 170): 11.325,81.575 11.35,81.6 11.55,81.6 11.575,81.575 11.575,81.3 12.725,80.153 12.725,79.225 12.675,79.175 10.675,79.175 10.625,79.225 10.625,79.975 11.325,80.675
5V_VIN on Top Layer "NO TR" (solid, remove dead copper, pour order 168): 10.925,81.575 10.95,81.6 11.15,81.6 11.175,81.575 11.175,80.725 10.5,80.05 10.5,78.475 7.95,78.475 7.775,78.65 7.775,79.025 7.9,79.15 8.825,79.15 9.175,79.5 9.438,79.75 9.701,79.75 9.75,79.801 9.75,80.338 10.925,81.451
5V_VIN on Top Layer "NO TR" (solid, remove dead copper, pour order 166): 14.425,78.575 14.325,78.475 13.075,78.475 13,78.55 13,80.075 12.525,80.55 12.525,81.575 12.55,81.6 12.75,81.6 12.775,81.575 12.775,81.293 14.425,79.656
NetL3_1 on Top Layer "NO TR" (solid, remove dead copper, pour order 164): 12.925,81.575 12.95,81.6 13.15,81.6 13.175,81.575 13.175,81.425 13.375,81.225 13.775,81.225 14.4,80.6 16.575,80.6 16.625,80.55 16.625,79.225 16.575,79.175 15.125,79.175 14.575,79.175 14.525,79.225 14.525,79.75 12.925,81.35
5V_VIN on Top Layer "NO TR" (solid, pour order 162): 8.675,89.05 7.588,89.05 6.475,89.95 6.475,90.15 5.7,90.15 5.7,88.425 5.85,88.275 8.6,88.275 10.35,86.525 10.75,86.525 10.75,87.45 9.875,88.325 9.35,88.325
VDD on Top Layer "NO TR" (solid, pour order 160): 10.3,86.45 10.3,86.175 9.475,86.175 8.525,87.125 7.95,87.125 7.9,87.175 7.9,88.075 7.975,88.15 8.6,88.15
VDD1_DDR on Top Layer "NO TR" (solid, remove dead copper, pour order 158): 9.7,85.775 7.875,85.775 7.7,85.95 7.7,86.7 7.875,86.875 8.65,86.875 9.075,86.45 9.55,85.975 9.7,85.975
NetL2_1 on Top Layer "NO TR" (solid, remove dead copper, pour order 156): 9.95,88.45 9.225,88.45 9.1,88.575 9.1,89.35 9.2,89.45 11.175,89.45 11.325,89.3 11.325,87.8 11.15,87.45 11.15,87.375 10.95,87.375 10.95,87.45
VDD2_DDR on Top Layer "NO TR" (solid, remove dead copper, pour order 154): 11.3,91.3 10.85,91.75 8.2,91.75 7.975,91.525 7.975,90.125 8.075,90.025 9.525,90.025 10.8,90.025 11.3,90.525
NetL1_1 on Top Layer "NO TR" (solid, remove dead copper, pour order 114): 12.75,87.1 12.75,87.575 13.3,88.125 14.05,88.125 14.325,88.4 14.325,90.35 14.15,90.525 13.25,90.525 13.1,90.375 13.1,88.975 12.55,88.425 12.55,87.1
GND on Top Layer "GND_L01_P182" (solid, remove dead copper, pour order 182): 55.3,71.325 55.3,65 89,65 89,120 0,120 0,45.675 0,0 89,0 89,65 55.3,64.999 55.3,53.95 37.8,53.95 36.6,55.15 35.25,56.5 35.225,56.475 25.775,56.475 25.5,56.75 25.5,68.5 25.75,68.75 29.25,68.75 29.25,69.25 28.25,70.25 28.25,83.75 25,83.75 25,91.5 25.25,91.75 32.5,91.75 32.75,91.5 32.75,86.5 34.25,85 34.25,72.5 33.75,72 33.75,69 34,68.75 35.5,68.75 38.075,71.325
GND on Signal Layer 1 "GND" (solid, remove dead copper, pour order 104): 0.408,119.592 89,119.592 89,0.408 0.408,0.408
5V_VIN on Signal Layer 4 "5V_VIN" (solid, remove dead copper, pour order 224): 17.65,85.3 17.65,84.775 19.3,84.775 19.3,79.825 17.875,78.4 4.4,78.4 4.4,90.15 7.9,90.15 7.9,87.375 11.325,87.375 11.325,90.15 16.325,90.15 16.325,85.3
VDD on Signal Layer 4 "VDD" (solid, remove dead copper, pour order 222): 16.126,74.8 16.126,74.751 16.126,74.625 16.126,71.05 23.625,59.475 32.75,59.475 32.75,60.841 31.114,62.375 25.907,62.375 18.355,75.025 16.274,75.025 16.126,74.9
VDD_CORE on Signal Layer 4 "VDD_CORE" (solid, remove dead copper, pour order 220): 26.225,84.05 20.775,89.5 18.1,89.5 18.1,92.3 26.475,92.3 29.375,89.4 32.725,86.048 32.725,61.409 31.65,61.409 31.65,62.025 31.156,62.5 26.225,62.5
VDD2_DDR on Signal Layer 4 "VDD2_DDR" (solid, remove dead copper, pour order 218): 33.2,90.475 31.025,92.65 13.15,92.65 10.3,89.8 8.125,89.8 8.125,91.775 11.85,95.5 28.475,95.5 33.825,95.5 39,90.325 39,69.65 52.775,69.65 52.775,53.8 33.2,53.8
GND on Signal Layer 4 "NETR16_2_L04_P-001" (solid, pour order 214): 40.5,90.25 40.5,79.5 51.25,79.5 51.5,79.75 41,90.25
GND on Signal Layer 4 "NETR16_2_L04_P-001" (solid, pour order 212): 20.25,88 21.25,88 25.5,83.75 25.5,66 25.25,65.75 25,65.75 24.5,66.25 19.5,74.75 22,77.25 22,85.5 20.25,87.25
GND on Signal Layer 4 "GND" (solid, pour order 230): 0,120 89,120 89,0 0,0
GND on Signal Layer 2 "GND" (solid, pour order 226): 0,120 89,120 89,0 0,0
GND on Signal Layer 3 "GND" (solid, pour order 232): 0,120 89,120 89,0 0,0
GND on Bottom Layer "GND" (solid, pour order 228): 0,120 89,120 89,0 0,0

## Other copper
Signal Layer 2:
  pour cut-out: 36.619,54.529 36.619,56.133 36.619,63.106 38.422,64.909 38.422,69.645 49.561,69.645 49.561,54.529 37.743,54.529
Signal Layer 3:
  pour cut-out: 34.929,65.769 34.929,63.231 39.17,58.989 52.132,58.989 52.132,64.552 50.727,65.957 49.153,67.53 38.376,67.53 35.71,66.55
Bottom Layer:
  pour cut-out: 35.075,68.975 52.999,68.975 52.999,57.875 35.075,57.875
